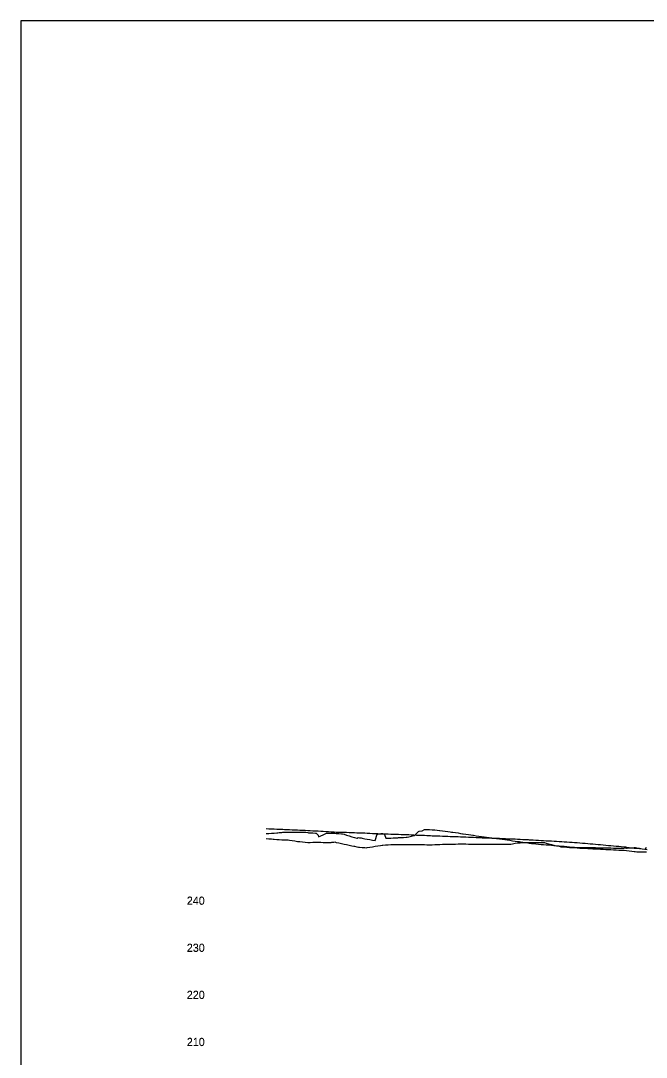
# Model space of a CAD drawing. Extents: x 2224795 to 2228395, y 930927 to 933127.
# Drawn here: x 2224795 to 2225458, y 932027 to 933127 of the extents above; entities that cross this region are included whole.
import ezdxf

# ---------------------------------------------------------------- set-up
doc = ezdxf.new("R2010")
doc.units = 0
for name, color, linetype in [('BR_EXIST_GROUND_LT', 7, 'Continuous'), ('BR_EXIST_GROUND_RT', 7, 'Continuous'), ('RD_DDB_ElevTX', 7, 'Continuous'), ('RD_DDB_Profile_EX', 7, 'Continuous'), ('RD_SHT_IplotShp', 7, 'Continuous')]:
    doc.layers.add(name, color=color, linetype=linetype)

msp = doc.modelspace()

# ---------------------------------------------------------------- linework, layer by layer
at = {"layer": 'BR_EXIST_GROUND_LT'}
msp.add_lwpolyline([(2225055.1, 932264.2), (2225056, 932264.1), (2225057.8, 932264.3), (2225060.6, 932264.5), (2225063.3, 932264.7), (2225066.1, 932264.9), (2225067.5, 932265.1), (2225068.8, 932265.2), (2225071.6, 932265.4), (2225072.7, 932265.5), (2225074.3, 932265.7), (2225074.7, 932265.7), (2225077.1, 932265.7), (2225079.8, 932265.7), (2225082.6, 932265.7), (2225085.3, 932265.7), (2225088.1, 932265.7), (2225090.8, 932265.7), (2225093.6, 932265.7), (2225096, 932265.7), (2225096.3, 932265.7), (2225097.2, 932265.6), (2225099.1, 932265.2), (2225099.9, 932265.1), (2225101.8, 932265), (2225104.5, 932264.9), (2225107.3, 932264.6), (2225108.1, 932264.6), (2225110.1, 932262.6), (2225110.6, 932260.6), (2225112.8, 932261.6), (2225115.6, 932262.9), (2225118.3, 932264.2), (2225119, 932264.5), (2225121.1, 932264.5), (2225123.8, 932264.5), (2225126.6, 932264.5), (2225127.9, 932264.5), (2225129.3, 932264.4), (2225132.1, 932264.2), (2225134.8, 932264), (2225136, 932263.9), (2225137.6, 932263.4), (2225140.3, 932262.5), (2225143.1, 932261.6), (2225145.8, 932260.8), (2225148.6, 932259.9), (2225151.3, 932259.1), (2225151.6, 932259.1), (2225152.7, 932260), (2225154.1, 932259.7), (2225155.6, 932259.5), (2225156.8, 932259.2), (2225159.6, 932258.7), (2225162.3, 932258.2), (2225165.1, 932257.7), (2225167.8, 932257.2), (2225170.7, 932256.7), (2225172.9, 932263.5), (2225173.3, 932263.6), (2225176.1, 932263.9), (2225177, 932264.1), (2225178.8, 932264.3), (2225180.1, 932264), (2225181.6, 932260.3), (2225182, 932259.1), (2225184.3, 932259.2), (2225187.1, 932259.3), (2225189.8, 932259.5), (2225192.6, 932259.6), (2225194.5, 932259.7), (2225195.3, 932259.8), (2225198.1, 932259.9), (2225200.8, 932260.1), (2225203.6, 932260.3), (2225204.7, 932260.3), (2225206.3, 932260.7), (2225207.8, 932261), (2225209.1, 932261.3), (2225211.8, 932262), (2225212.5, 932262.1), (2225214.6, 932264.4), (2225216.5, 932266.5), (2225217.3, 932266.7), (2225220.1, 932267.1), (2225220.6, 932267.2), (2225222.8, 932268.3), (2225223.3, 932268.5), (2225225.6, 932268.5), (2225227.6, 932268.5), (2225228.3, 932268.4), (2225231.1, 932268.2), (2225233.8, 932268), (2225236.5, 932267.7), (2225238.9, 932267.5), (2225239.3, 932267.4), (2225242.1, 932267.1), (2225244.8, 932266.7), (2225247.6, 932266.3), (2225250.3, 932266), (2225251.7, 932265.8), (2225253.1, 932265.6), (2225255.8, 932265.2), (2225258.6, 932264.8), (2225261.3, 932264.3), (2225263.4, 932264), (2225264.1, 932263.9), (2225266.8, 932263.5), (2225269.6, 932263.1), (2225272.3, 932262.7), (2225274.1, 932262.5), (2225275.1, 932262.3), (2225277.8, 932261.9), (2225280.6, 932261.5), (2225283.5, 932261), (2225286.1, 932260.7), (2225288.8, 932260.3), (2225291.6, 932260), (2225294.3, 932259.6), (2225297.1, 932259.3), (2225299.2, 932259), (2225299.8, 932258.9), (2225302.6, 932258.5), (2225305.3, 932258.1), (2225308.1, 932257.8), (2225310.8, 932257.4), (2225313.6, 932257), (2225316.3, 932256.6), (2225319.1, 932256.2), (2225321.8, 932255.8), (2225323.4, 932255.6), (2225324.6, 932255.4), (2225327.3, 932255), (2225330.1, 932254.6), (2225332.5, 932254.2), (2225332.8, 932254.2), (2225334.2, 932254), (2225335.6, 932253.8), (2225336.5, 932253.6), (2225338.3, 932253.5), (2225341.1, 932253.2), (2225343.8, 932253), (2225346.6, 932252.7), (2225347, 932252.6), (2225349.3, 932252.5), (2225352.1, 932252.3), (2225354.8, 932252.1), (2225357.6, 932251.8), (2225360.3, 932251.6), (2225361, 932251.6), (2225363.1, 932251.3), (2225365.8, 932251.1), (2225367.4, 932250.9), (2225368.6, 932250.8), (2225371.3, 932250.6), (2225374.1, 932250.3), (2225376.8, 932250.1), (2225379.6, 932249.8), (2225382.3, 932249.6), (2225385.1, 932249.3), (2225385.5, 932249.3), (2225387.4, 932249.3), (2225387.8, 932249.4), (2225390.6, 932249.4), (2225391.7, 932249.4), (2225393.3, 932249.4), (2225396.1, 932249.3), (2225398.8, 932249.3), (2225401.6, 932249.2), (2225404.3, 932249.2), (2225407.1, 932249.1), (2225409.8, 932249.1), (2225412.6, 932249), (2225415.3, 932248.9), (2225418.1, 932248.9), (2225420.8, 932248.9), (2225423.6, 932248.8), (2225426.3, 932248.8), (2225429.1, 932248.7), (2225431.8, 932248.7), (2225433.3, 932248.6), (2225434.6, 932248.8), (2225435.7, 932248.9), (2225437.3, 932248.8), (2225437.9, 932248.8), (2225438.7, 932249.1), (2225440.1, 932249.1), (2225442.8, 932249.1), (2225445.6, 932249.2), (2225446.9, 932249.2), (2225448.3, 932249), (2225451.1, 932248.5), (2225453.8, 932248), (2225456.6, 932247.5), (2225457.2, 932247.4), (2225458.4, 932249.7)], dxfattribs=at)
at = {"layer": 'BR_EXIST_GROUND_RT'}
msp.add_lwpolyline([(2225055.1, 932259), (2225057.8, 932258.7), (2225060.6, 932258.4), (2225062.4, 932258.2), (2225063.3, 932258.1), (2225066.1, 932257.9), (2225068.8, 932257.7), (2225071.6, 932257.6), (2225072.6, 932257.5), (2225073.6, 932257.4), (2225074.3, 932257.4), (2225077.1, 932257.4), (2225078.4, 932257.4), (2225079.8, 932257.1), (2225082.6, 932256.7), (2225085.3, 932256.3), (2225088.1, 932255.9), (2225090.8, 932255.6), (2225093.6, 932255.2), (2225096.3, 932254.9), (2225099.1, 932254.6), (2225101.8, 932254.7), (2225104.6, 932254.9), (2225107.3, 932255), (2225108, 932255.1), (2225110.1, 932255), (2225112.8, 932254.9), (2225115.6, 932254.8), (2225118.3, 932254.8), (2225121.1, 932254.8), (2225123.8, 932254.8), (2225124.5, 932254.9), (2225125.8, 932254.9), (2225126.6, 932255), (2225127.8, 932255.2), (2225129.3, 932254.8), (2225132.1, 932254.2), (2225134.8, 932253.5), (2225137.6, 932252.9), (2225140.3, 932252.4), (2225143.1, 932251.8), (2225145.8, 932251.3), (2225148, 932250.9), (2225148.6, 932250.8), (2225151.3, 932250.2), (2225152.9, 932249.8), (2225154.1, 932249.7), (2225156.8, 932249.4), (2225159.6, 932249.2), (2225161.1, 932249), (2225162.3, 932249.2), (2225165.1, 932249.7), (2225167.8, 932250.2), (2225170.6, 932250.7), (2225173.3, 932251.1), (2225176.1, 932251.5), (2225177.9, 932251.8), (2225178.3, 932251.8), (2225178.8, 932251.9), (2225181.6, 932252.1), (2225184.3, 932252.2), (2225187.1, 932252.4), (2225189.8, 932252.6), (2225192.6, 932252.6), (2225195.3, 932252.6), (2225198.1, 932252.6), (2225200.8, 932252.6), (2225203.6, 932252.5), (2225204.2, 932252.5), (2225206.3, 932252.6), (2225209.1, 932252.6), (2225211.8, 932252.7), (2225214.6, 932252.6), (2225217.3, 932252.5), (2225220.1, 932252.5), (2225222.8, 932252.4), (2225225.6, 932252.3), (2225228.3, 932252.2), (2225230, 932252.1), (2225231.1, 932252.2), (2225233.8, 932252.4), (2225236.6, 932252.6), (2225238, 932252.7), (2225239.3, 932252.7), (2225242.1, 932252.8), (2225244.8, 932252.8), (2225247.6, 932252.9), (2225250.3, 932252.9), (2225253.1, 932252.9), (2225255.8, 932252.9), (2225258.6, 932253.1), (2225259, 932253.1), (2225261.3, 932253.1), (2225264.1, 932253.1), (2225266.8, 932253.1), (2225269.6, 932253), (2225272.3, 932253), (2225275.1, 932253), (2225277.8, 932252.9), (2225280.6, 932252.9), (2225281.2, 932252.9), (2225283.3, 932252.9), (2225283.7, 932252.9), (2225284.1, 932252.9), (2225286.1, 932252.9), (2225288.8, 932252.9), (2225291.6, 932252.9), (2225294.3, 932252.9), (2225297.1, 932252.9), (2225299.8, 932252.9), (2225302.6, 932252.9), (2225305.3, 932252.9), (2225308.1, 932252.8), (2225308.8, 932252.8), (2225310.8, 932252.8), (2225313.6, 932252.8), (2225314.6, 932252.8), (2225316.3, 932253.2), (2225319.1, 932253.8), (2225321.6, 932254.3), (2225323.1, 932254.3), (2225324.6, 932254.4), (2225327.3, 932254.5), (2225330.1, 932254.7), (2225332.2, 932254.8), (2225332.8, 932254.8), (2225335.6, 932254.7), (2225338.3, 932254.7), (2225341.1, 932254.7), (2225341.9, 932254.7), (2225342.4, 932254.7), (2225342.8, 932254.7), (2225343.8, 932254.7), (2225346.6, 932254.7), (2225349.3, 932254.5), (2225350.2, 932254.5), (2225352.1, 932254), (2225354.8, 932253.3), (2225357.6, 932252.6), (2225360.3, 932251.9), (2225363.1, 932251.3), (2225365.8, 932250.6), (2225367.7, 932250.1), (2225368.6, 932250.1), (2225370.5, 932249.9), (2225371.3, 932249.9), (2225374.1, 932249.7), (2225376.8, 932249.5), (2225379.6, 932249.3), (2225382.3, 932249.2), (2225385.1, 932249), (2225387.8, 932248.8), (2225390.6, 932248.6), (2225391.6, 932248.6), (2225393.3, 932248.5), (2225396.1, 932248.4), (2225398.8, 932248.2), (2225401.6, 932248.1), (2225404.3, 932248), (2225407.1, 932247.9), (2225409.8, 932247.7), (2225410.6, 932247.7), (2225412.6, 932247.6), (2225415.3, 932247.4), (2225416.7, 932247.3), (2225418.1, 932247.2), (2225420.8, 932247.1), (2225423.6, 932247), (2225426.3, 932246.9), (2225429.1, 932246.7), (2225431.8, 932246.6), (2225434.9, 932246.5), (2225437.3, 932246.2), (2225440.1, 932245.8), (2225442.8, 932245.5), (2225445.6, 932245.1), (2225446.6, 932245), (2225448.3, 932244.9), (2225451.1, 932244.7), (2225452.6, 932244.6), (2225453.8, 932244.6), (2225456.6, 932244.7), (2225458.7, 932244.7)], dxfattribs=at)
at = {"layer": 'RD_DDB_Profile_EX'}
msp.add_lwpolyline([(2225055.1, 932269.4), (2225057.8, 932269.3), (2225060.6, 932269.2), (2225063.3, 932269.1), (2225066.1, 932269), (2225068.8, 932268.8), (2225071.6, 932268.7), (2225072.5, 932268.7), (2225074.3, 932268.6), (2225075.2, 932268.5), (2225075.6, 932268.5), (2225077.1, 932268.4), (2225079.8, 932268.3), (2225082.6, 932268.2), (2225085.3, 932268.1), (2225088.1, 932268), (2225090.8, 932267.8), (2225093.6, 932267.7), (2225096.3, 932267.6), (2225099.1, 932267.4), (2225100.2, 932267.4), (2225101.1, 932267.3), (2225101.8, 932267.3), (2225104.6, 932267.2), (2225107.3, 932267), (2225110.1, 932266.9), (2225112.8, 932266.7), (2225115.6, 932266.6), (2225118.3, 932266.4), (2225121.2, 932266.2), (2225123.8, 932266.1), (2225125.2, 932266), (2225126.6, 932265.9), (2225127.1, 932265.9), (2225129.3, 932265.8), (2225132.1, 932265.7), (2225133, 932265.7), (2225134.8, 932265.6), (2225137.6, 932265.6), (2225140.3, 932265.5), (2225143.1, 932265.4), (2225145.8, 932265.3), (2225148.6, 932265.2), (2225151.3, 932265.1), (2225152.1, 932265.1), (2225153, 932265), (2225154.1, 932265), (2225156.8, 932264.9), (2225159.6, 932264.8), (2225162.3, 932264.7), (2225165.1, 932264.5), (2225167.8, 932264.4), (2225170.6, 932264.3), (2225173.3, 932264.2), (2225176.1, 932264), (2225177.1, 932264), (2225178.8, 932263.9), (2225179.4, 932263.9), (2225181.6, 932263.8), (2225184.3, 932263.7), (2225187.1, 932263.6), (2225189.8, 932263.6), (2225192.6, 932263.5), (2225195.3, 932263.4), (2225198.1, 932263.3), (2225200.8, 932263.2), (2225202.3, 932263.1), (2225203.6, 932263.1), (2225204.4, 932263.1), (2225206.3, 932263), (2225209.1, 932262.9), (2225211.8, 932262.8), (2225214.6, 932262.6), (2225217.3, 932262.5), (2225220.1, 932262.4), (2225222.8, 932262.3), (2225225.6, 932262.2), (2225227.1, 932262.1), (2225228.3, 932262), (2225229.4, 932262), (2225231.1, 932261.9), (2225231.7, 932261.9), (2225233.8, 932261.8), (2225236.6, 932261.7), (2225239.3, 932261.6), (2225242.1, 932261.5), (2225244.8, 932261.4), (2225247.6, 932261.3), (2225250.3, 932261.2), (2225253.1, 932261.1), (2225253.5, 932261.1), (2225255.8, 932261), (2225256.7, 932261), (2225258.6, 932260.9), (2225261.3, 932260.8), (2225264.1, 932260.7), (2225266.8, 932260.6), (2225269.6, 932260.4), (2225272.3, 932260.3), (2225275.1, 932260.2), (2225277.8, 932260.1), (2225278.8, 932260), (2225280.6, 932259.9), (2225281.7, 932259.9), (2225283.3, 932259.8), (2225284, 932259.7), (2225286.1, 932259.7), (2225286.8, 932259.7), (2225288.8, 932259.6), (2225291.6, 932259.5), (2225294.3, 932259.4), (2225297.1, 932259.3), (2225299.8, 932259.2), (2225302.6, 932259.1), (2225305.3, 932259), (2225308.1, 932258.9), (2225309, 932258.8), (2225310.8, 932258.7), (2225312.2, 932258.7), (2225313.6, 932258.6), (2225316.3, 932258.5), (2225319.1, 932258.4), (2225321.8, 932258.2), (2225324.6, 932258.1), (2225327.3, 932258), (2225330.1, 932257.8), (2225332.8, 932257.7), (2225334.2, 932257.6), (2225335.6, 932257.5), (2225337.7, 932257.4), (2225338.3, 932257.4), (2225341.1, 932257.2), (2225343.8, 932257.1), (2225346.6, 932256.9), (2225349.3, 932256.8), (2225352.1, 932256.6), (2225354.8, 932256.5), (2225357.6, 932256.3), (2225360.4, 932256.1), (2225363.1, 932256), (2225365.8, 932255.8), (2225368.6, 932255.6), (2225371.3, 932255.5), (2225374.1, 932255.3), (2225376.8, 932255.1), (2225379.6, 932254.9), (2225382.3, 932254.7), (2225384.1, 932254.6), (2225385.1, 932254.5), (2225387.8, 932254.3), (2225390.6, 932254.1), (2225393.3, 932253.8), (2225396.1, 932253.6), (2225398.8, 932253.4), (2225401.6, 932253.1), (2225404.3, 932252.9), (2225407.1, 932252.6), (2225408.4, 932252.5), (2225409.8, 932252.4), (2225412.6, 932252.1), (2225415.3, 932251.9), (2225418.1, 932251.6), (2225420.8, 932251.4), (2225423.6, 932251.1), (2225426.3, 932250.8), (2225429.1, 932250.6), (2225431.8, 932250.3), (2225434.8, 932250), (2225435.7, 932249.9), (2225436.1, 932249.9), (2225437.3, 932249.8), (2225440.1, 932249.4), (2225442.8, 932249.1), (2225445.6, 932248.8), (2225448.3, 932248.5), (2225451.1, 932248.2), (2225453.8, 932247.9), (2225456.6, 932247.6), (2225459.3, 932247.3)], dxfattribs=at)
at = {"layer": 'RD_SHT_IplotShp'}
msp.add_lwpolyline([(2228394.5, 933127.2), (2224794.5, 933127.2), (2224794.5, 930927.2), (2228394.5, 930927.2)], close=True, dxfattribs=at)

# ---------------------------------------------------------------- texts
at = {"layer": 'RD_DDB_ElevTX'}
for s, p in [('240', (2224970.8, 932188.8)), ('240', (2224970.8, 932188.5)), ('230', (2224970.8, 932138.8)), ('230', (2224970.8, 932138.5)), ('220', (2224970.8, 932088.8)), ('220', (2224970.8, 932088.5)), ('210', (2224970.8, 932038.8)), ('210', (2224970.8, 932038.5))]:
    msp.add_text(s, height=8.5, dxfattribs=at).set_placement(p)

doc.saveas('drawing.dxf')
